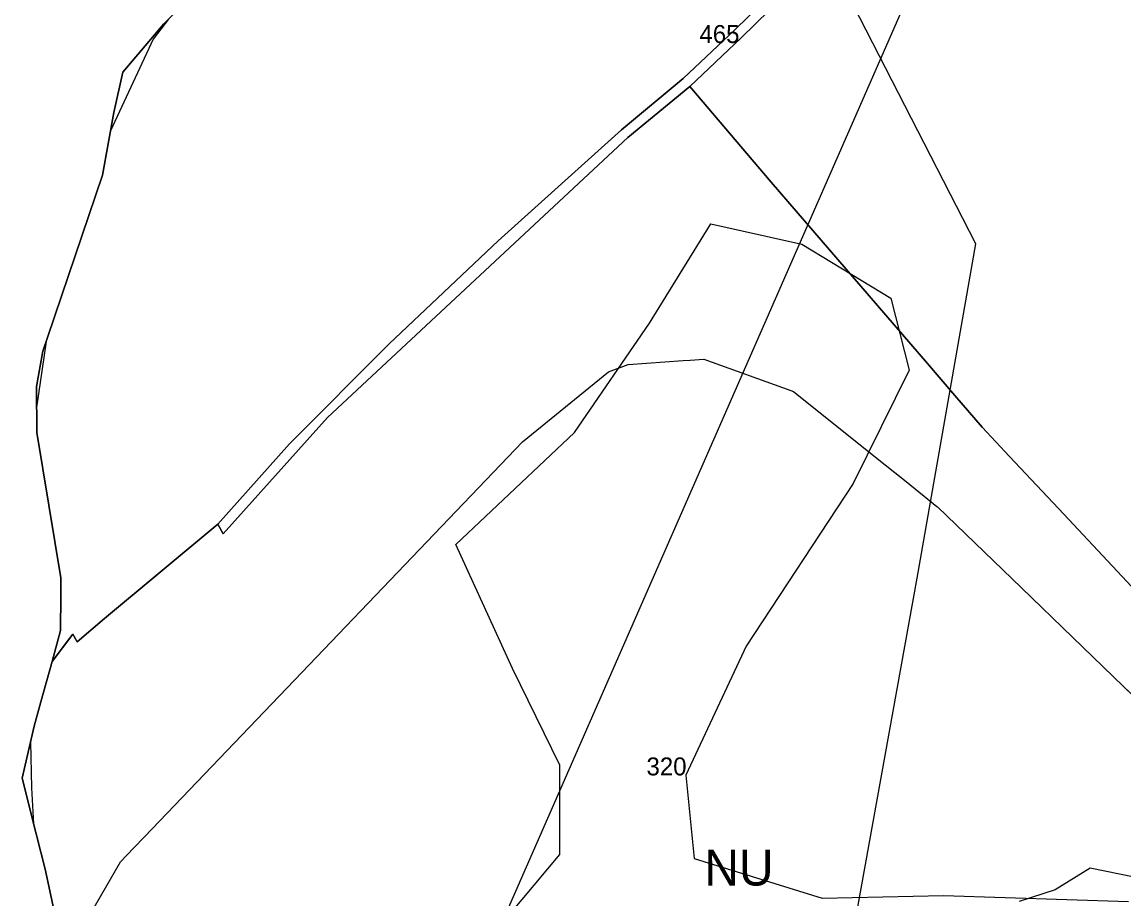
# Model space of a CAD drawing. Extents: x -690419 to -685080, y -987825 to -981190.
# Drawn here: x -688519.4 to -688212.4, y -984484.8 to -984240.6 of the extents above; entities that cross this region are included whole.
import ezdxf

# ---------------------------------------------------------------- set-up
doc = ezdxf.new("R2010")
doc.units = 0
for name, color, linetype in [('BPEJ (S) - hranice', 7, 'Continuous'), ('Hranice řešeného území (S)', 7, 'Continuous'), ('Investice do půdy_hlavní odvodňovací zařízení zatrubněné S', 7, 'Continuous'), ('Investice do půdy_odvodnění (S)', 7, 'Continuous'), ('Katastrální území (S) - hranice', 7, 'Continuous'), ('Plochy přírodní všeobecné NU (S)', 7, 'Continuous'), ('Plochy smíšené nezastavěného území všeobecné MU (S)', 7, 'Continuous'), ('Plochy zemědělské všeobecné AU (S)', 7, 'Continuous'), ('Regulacni bloky_ID', 7, 'Continuous'), ('Regulační bloky STABILIZOVANÉ (S)', 7, 'Continuous'), ('Regulační kódy STABILIZOVANÉ (S)', 7, 'Continuous'), ('Spoje - MW trasy', 7, 'Continuous'), ('USES LBC (S)', 7, 'Continuous'), ('USES_ŠRAFY (S)', 7, 'Continuous')]:
    doc.layers.add(name, color=color, linetype=linetype)

msp = doc.modelspace()

# ---------------------------------------------------------------- linework, layer by layer
at = {"layer": 'BPEJ (S) - hranice'}
for p, q in [((-688329.5, -984334.5), (-688305.25, -984343.23)), ((-688380, -984357.5), (-688356, -984338)), ((-688212.48, -984425.66), (-688194.5, -984443))]:
    msp.add_line(p, q, dxfattribs=at)
for points in [[(-688451.12, -984212.71), (-688479.92, -984241.13), (-688491.32, -984254.62), (-688493.88, -984265.86), (-688496.96, -984283.24), (-688512.25, -984328.23), (-688513.61, -984332.24), (-688515.42, -984342.1), (-688515.34, -984354.96), (-688508.59, -984395.38), (-688508.63, -984401.8), (-688508.67, -984408.61), (-688508.68, -984410.07), (-688511.07, -984418.68), (-688514.19, -984429.94), (-688516.06, -984436.68), (-688519.42, -984451.17), (-688518.03, -984456.68), (-688516.68, -984462), (-688512.97, -984476.55), (-688510.04, -984490.37), (-688507.09, -984504.27), (-688505.49, -984511.8), (-688505.45, -984512.12)], [(-688505.5, -984498), (-688492, -984474.5), (-688488.28, -984470.61), (-688485.32, -984467.52), (-688441.49, -984421.74), (-688380, -984357.5), (-688356, -984338), (-688350.5, -984336), (-688335.25, -984334.91), (-688333.22, -984334.77), (-688329.5, -984334.5), (-688305.25, -984343.23), (-688304.5, -984343.5), (-688282.09, -984361.42), (-688273.12, -984368.6), (-688264.5, -984375.5), (-688264.37, -984375.62), (-688256.52, -984383.19), (-688240.96, -984398.2), (-688212.48, -984425.66), (-688194.5, -984443)], [(-688356, -984338), (-688350.5, -984336), (-688335.25, -984334.91)], [(-688335.25, -984334.91), (-688333.22, -984334.77), (-688329.5, -984334.5)], [(-688305.25, -984343.23), (-688304.5, -984343.5), (-688282.09, -984361.42)], [(-688485.32, -984467.52), (-688441.49, -984421.74), (-688380, -984357.5)], [(-688282.09, -984361.42), (-688273.12, -984368.6), (-688264.5, -984375.5), (-688264.37, -984375.62)], [(-688264.37, -984375.62), (-688256.52, -984383.19), (-688240.96, -984398.2), (-688212.48, -984425.66)], [(-688505.45, -984512.12), (-688504.03, -984509.48), (-688503.5, -984508.5), (-688505.5, -984498), (-688492, -984474.5), (-688488.28, -984470.61), (-688485.32, -984467.52)], [(-688205.49, -984479.62), (-688221.81, -984476.24), (-688231.6, -984482.26), (-688241.56, -984485.55)]]:
    msp.add_lwpolyline(points, dxfattribs=at)
at = {"layer": 'Hranice řešeného území (S)'}
msp.add_lwpolyline([(-688510.04, -984490.37), (-688512.97, -984476.55), (-688516.68, -984462), (-688518.03, -984456.68), (-688519.42, -984451.17), (-688516.06, -984436.68), (-688514.19, -984429.94), (-688511.07, -984418.68), (-688508.68, -984410.07), (-688508.67, -984408.61), (-688508.63, -984401.8), (-688508.59, -984395.38), (-688515.34, -984354.96), (-688515.42, -984342.1), (-688513.61, -984332.24), (-688512.25, -984328.23), (-688496.96, -984283.24), (-688493.88, -984265.86), (-688491.32, -984254.62), (-688479.92, -984241.13), (-688451.12, -984212.71)], dxfattribs=at)
at = {"layer": 'Investice do půdy_hlavní odvodňovací zařízení zatrubněné S'}
msp.add_lwpolyline([(-688287.85, -984494.25), (-688269.99, -984395.46), (-688253.67, -984302.39), (-688291.41, -984228.84), (-688261.25, -984190.21), (-688221.3, -984140.74), (-688188.32, -984136.51)], dxfattribs=at)
at = {"layer": 'Investice do půdy_odvodnění (S)'}
msp.add_line((-688512.7, -984329.55), (-688515.38, -984347.99), dxfattribs=at)
for points in [[(-688478.63, -984239.85), (-688482.85, -984245.39), (-688494.78, -984270.96)], [(-688494.78, -984270.96), (-688496.96, -984283.24), (-688512.25, -984328.23), (-688512.7, -984329.55)], [(-688481.45, -984641.95), (-688454.42, -984610.02), (-688439.8, -984590.16), (-688417.2, -984541.73), (-688401.03, -984510.05), (-688369.54, -984472.47), (-688369.6, -984447.56), (-688382.73, -984420.64), (-688398.56, -984386.13), (-688365.48, -984354.96), (-688344.61, -984324.51), (-688327.5, -984296.81), (-688302.11, -984302.48), (-688277.38, -984317.55), (-688272.21, -984337.6), (-688287.84, -984369.11), (-688317.67, -984414.39), (-688334.5, -984450.34), (-688332.12, -984473.56), (-688296.49, -984484.64), (-688262.65, -984483.89), (-688211.17, -984485.58)], [(-688515.38, -984347.99), (-688515.34, -984354.96), (-688508.59, -984395.38), (-688508.63, -984401.8), (-688508.67, -984408.61), (-688508.68, -984410.07), (-688511.07, -984418.68), (-688514.19, -984429.94), (-688516.06, -984436.68), (-688517.08, -984441.09)], [(-688517.08, -984441.09), (-688516.78, -984453.87), (-688516.2, -984463.89)], [(-688516.2, -984463.89), (-688512.97, -984476.55), (-688510.04, -984490.37), (-688507.09, -984504.27), (-688505.49, -984511.8), (-688502.99, -984530.58), (-688502.72, -984532.63), (-688500.95, -984546), (-688500.08, -984552.55), (-688496.2, -984562.92), (-688492.04, -984574.01), (-688494.32, -984588.16), (-688497.68, -984609.01)]]:
    msp.add_lwpolyline(points, dxfattribs=at)
at = {"layer": 'Katastrální území (S) - hranice'}
msp.add_lwpolyline([(-688451.12, -984212.71), (-688479.92, -984241.13), (-688491.32, -984254.62), (-688493.88, -984265.86), (-688496.96, -984283.24), (-688512.25, -984328.23), (-688513.61, -984332.24), (-688515.42, -984342.1), (-688515.34, -984354.96), (-688508.59, -984395.38), (-688508.63, -984401.8), (-688508.67, -984408.61), (-688508.68, -984410.07), (-688511.07, -984418.68), (-688514.19, -984429.94), (-688516.06, -984436.68), (-688519.42, -984451.17), (-688518.03, -984456.68), (-688516.68, -984462), (-688512.97, -984476.55), (-688510.04, -984490.37)], dxfattribs=at)
at = {"layer": 'Plochy přírodní všeobecné NU (S)'}
msp.add_lwpolyline([(-688510.04, -984490.37), (-688512.97, -984476.55), (-688516.68, -984462), (-688518.03, -984456.68), (-688519.42, -984451.17), (-688516.06, -984436.68), (-688514.19, -984429.94), (-688511.07, -984418.68), (-688506.85, -984413.09), (-688505.3, -984411.07), (-688504.07, -984413.23), (-688496.44, -984406.77), (-688464.89, -984380.5), (-688463.41, -984383.11), (-688434.3, -984350.74), (-688350.63, -984272.75), (-688333.33, -984258.62), (-688310.66, -984285.19), (-688267.14, -984335.75), (-688259.5, -984344.63), (-688251.93, -984353.43), (-688244.28, -984361.58), (-688229.17, -984377.69), (-688202.14, -984406.52)], dxfattribs=at)
at = {"layer": 'Plochy smíšené nezastavěného území všeobecné MU (S)'}
msp.add_lwpolyline([(-688096.34, -984204.36), (-688215.15, -984124.66), (-688244.91, -984160.62), (-688283.72, -984205.64), (-688299.38, -984225.7), (-688319.09, -984245.01), (-688333.33, -984258.62), (-688350.63, -984272.75), (-688434.3, -984350.74), (-688463.41, -984383.11), (-688464.89, -984380.5), (-688444.89, -984358.12), (-688417.17, -984330.26), (-688386.77, -984301.57), (-688352.42, -984270.6), (-688335.25, -984256.31), (-688320.86, -984242.81), (-688302.04, -984224.42), (-688286.45, -984204.39), (-688247.24, -984158.13), (-688221.07, -984121.18), (-688223.2, -984112.33), (-688201.56, -984127.44)], dxfattribs=at)
at = {"layer": 'Plochy zemědělské všeobecné AU (S)'}
for points in [[(-688202.14, -984406.52), (-688229.17, -984377.69), (-688244.28, -984361.58), (-688251.93, -984353.43), (-688259.5, -984344.63), (-688267.14, -984335.75), (-688310.66, -984285.19), (-688333.33, -984258.62), (-688319.09, -984245.01), (-688299.38, -984225.7), (-688283.72, -984205.64), (-688244.91, -984160.62), (-688215.15, -984124.66), (-688096.34, -984204.36)], [(-688302.04, -984224.42), (-688320.86, -984242.81), (-688335.25, -984256.31), (-688352.42, -984270.6), (-688386.77, -984301.57), (-688417.17, -984330.26), (-688444.89, -984358.12), (-688464.89, -984380.5), (-688496.44, -984406.77), (-688504.07, -984413.23), (-688505.3, -984411.07), (-688506.85, -984413.09), (-688511.07, -984418.68), (-688508.68, -984410.07), (-688508.67, -984408.61), (-688508.63, -984401.8), (-688508.59, -984395.38), (-688515.34, -984354.96), (-688515.42, -984342.1), (-688513.61, -984332.24), (-688512.25, -984328.23), (-688496.96, -984283.24), (-688493.88, -984265.86), (-688491.32, -984254.62), (-688479.92, -984241.13), (-688451.12, -984212.71)]]:
    msp.add_lwpolyline(points, dxfattribs=at)
at = {"layer": 'Regulační bloky STABILIZOVANÉ (S)'}
for points in [[(-688096.34, -984204.36), (-688215.15, -984124.66), (-688244.91, -984160.62), (-688283.72, -984205.64), (-688299.38, -984225.7), (-688319.09, -984245.01), (-688333.33, -984258.62), (-688350.63, -984272.75), (-688434.3, -984350.74), (-688463.41, -984383.11), (-688464.89, -984380.5), (-688444.89, -984358.12), (-688417.17, -984330.26), (-688386.77, -984301.57), (-688352.42, -984270.6), (-688335.25, -984256.31), (-688320.86, -984242.81), (-688302.04, -984224.42), (-688286.45, -984204.39), (-688247.24, -984158.13), (-688221.07, -984121.18), (-688223.2, -984112.33), (-688201.56, -984127.44)], [(-688202.14, -984406.52), (-688229.17, -984377.69), (-688244.28, -984361.58), (-688251.93, -984353.43), (-688259.5, -984344.63), (-688267.14, -984335.75), (-688310.66, -984285.19), (-688333.33, -984258.62), (-688319.09, -984245.01), (-688299.38, -984225.7), (-688283.72, -984205.64), (-688244.91, -984160.62), (-688215.15, -984124.66), (-688096.34, -984204.36)], [(-688302.04, -984224.42), (-688320.86, -984242.81), (-688335.25, -984256.31), (-688352.42, -984270.6), (-688386.77, -984301.57), (-688417.17, -984330.26), (-688444.89, -984358.12), (-688464.89, -984380.5), (-688496.44, -984406.77), (-688504.07, -984413.23), (-688505.3, -984411.07), (-688506.85, -984413.09), (-688511.07, -984418.68), (-688508.68, -984410.07), (-688508.67, -984408.61), (-688508.63, -984401.8), (-688508.59, -984395.38), (-688515.34, -984354.96), (-688515.42, -984342.1), (-688513.61, -984332.24), (-688512.25, -984328.23), (-688496.96, -984283.24), (-688493.88, -984265.86), (-688491.32, -984254.62), (-688479.92, -984241.13), (-688451.12, -984212.71)], [(-688510.04, -984490.37), (-688512.97, -984476.55), (-688516.68, -984462), (-688518.03, -984456.68), (-688519.42, -984451.17), (-688516.06, -984436.68), (-688514.19, -984429.94), (-688511.07, -984418.68), (-688506.85, -984413.09), (-688505.3, -984411.07), (-688504.07, -984413.23), (-688496.44, -984406.77), (-688464.89, -984380.5), (-688463.41, -984383.11), (-688434.3, -984350.74), (-688350.63, -984272.75), (-688333.33, -984258.62), (-688310.66, -984285.19), (-688267.14, -984335.75), (-688259.5, -984344.63), (-688251.93, -984353.43), (-688244.28, -984361.58), (-688229.17, -984377.69), (-688202.14, -984406.52)]]:
    msp.add_lwpolyline(points, dxfattribs=at)
at = {"layer": 'Spoje - MW trasy'}
msp.add_lwpolyline([(-688164.9, -983987.83), (-688465.48, -984673.28)], dxfattribs=at)
at = {"layer": 'USES LBC (S)'}
msp.add_lwpolyline([(-688202.14, -984406.52), (-688229.17, -984377.69), (-688244.28, -984361.58), (-688251.93, -984353.43), (-688259.5, -984344.63), (-688267.14, -984335.75), (-688310.66, -984285.19), (-688333.33, -984258.62), (-688350.63, -984272.75), (-688434.3, -984350.74), (-688463.41, -984383.11), (-688464.89, -984380.5), (-688496.44, -984406.77), (-688504.07, -984413.23), (-688505.3, -984411.07), (-688511.07, -984418.68), (-688514.19, -984429.94), (-688516.06, -984436.68), (-688519.42, -984451.17), (-688518.03, -984456.68), (-688516.68, -984462), (-688512.97, -984476.55), (-688507.09, -984504.27)], dxfattribs=at)
at = {"layer": 'USES_ŠRAFY (S)'}
msp.add_lwpolyline([(-688202.14, -984406.52), (-688229.17, -984377.69), (-688244.28, -984361.58), (-688251.93, -984353.43), (-688259.5, -984344.63), (-688267.14, -984335.75), (-688310.66, -984285.19), (-688333.33, -984258.62), (-688350.63, -984272.75), (-688434.3, -984350.74), (-688463.41, -984383.11), (-688464.89, -984380.5), (-688496.44, -984406.77), (-688504.07, -984413.23), (-688505.3, -984411.07), (-688511.07, -984418.68), (-688514.19, -984429.94), (-688516.06, -984436.68), (-688519.42, -984451.17), (-688518.03, -984456.68), (-688516.68, -984462), (-688512.97, -984476.55), (-688507.09, -984504.27)], dxfattribs=at)

# ---------------------------------------------------------------- texts
at = {"layer": 'Regulacni bloky_ID'}
for s, p in [('465', (-688330.68, -984246.47)), ('320', (-688345.43, -984450.42))]:
    msp.add_text(s, height=5, dxfattribs=at).set_placement(p)
at = {"layer": 'Regulační kódy STABILIZOVANÉ (S)'}
msp.add_text('NU', height=10, dxfattribs=at).set_placement((-688329.33, -984481.1))

doc.saveas('drawing.dxf')
